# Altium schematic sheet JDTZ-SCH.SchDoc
size A1
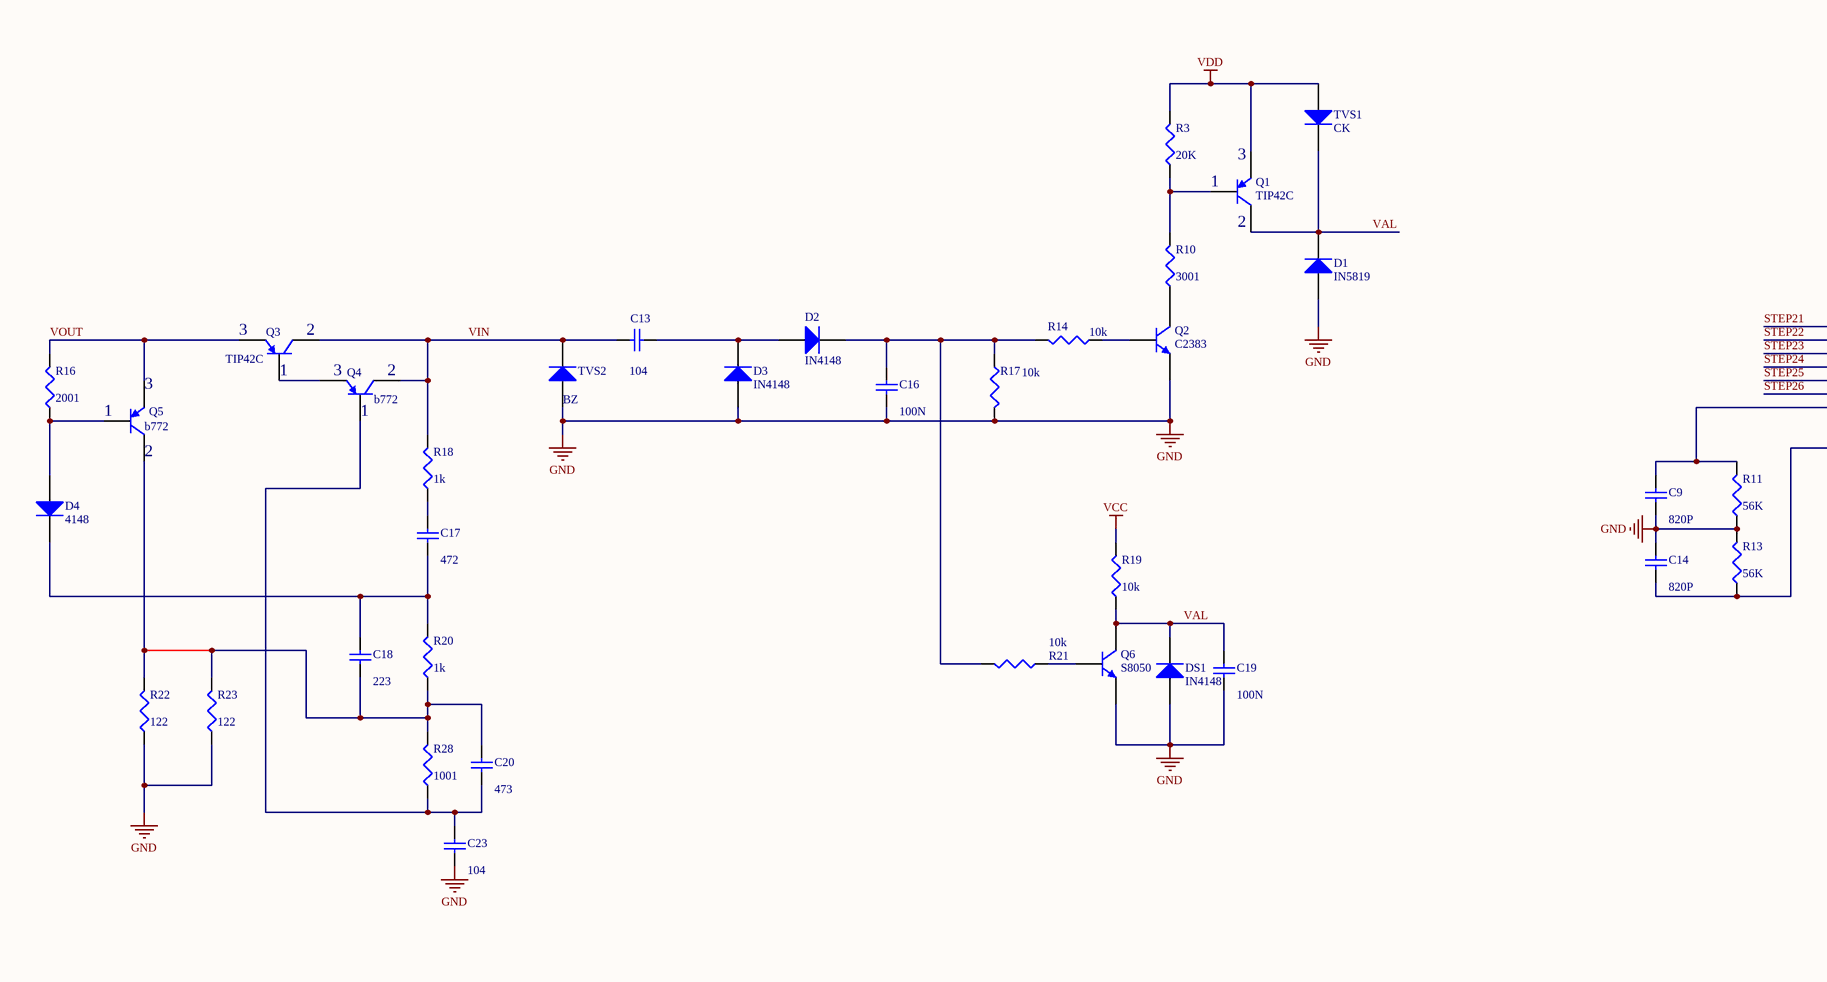
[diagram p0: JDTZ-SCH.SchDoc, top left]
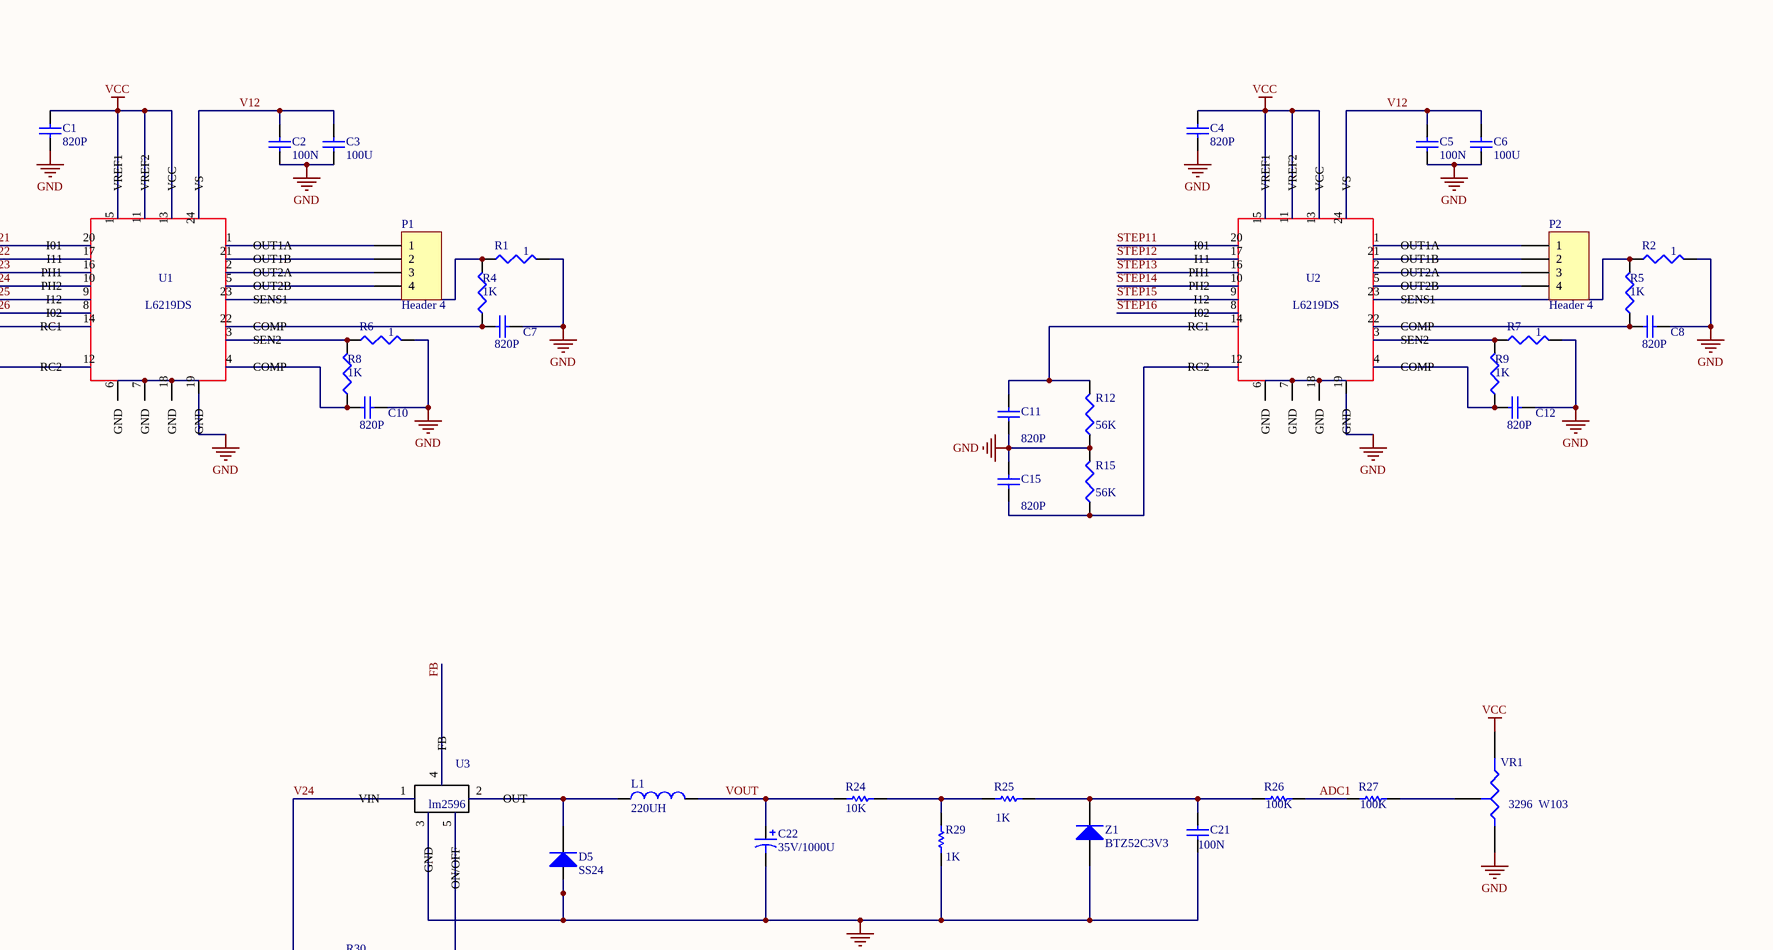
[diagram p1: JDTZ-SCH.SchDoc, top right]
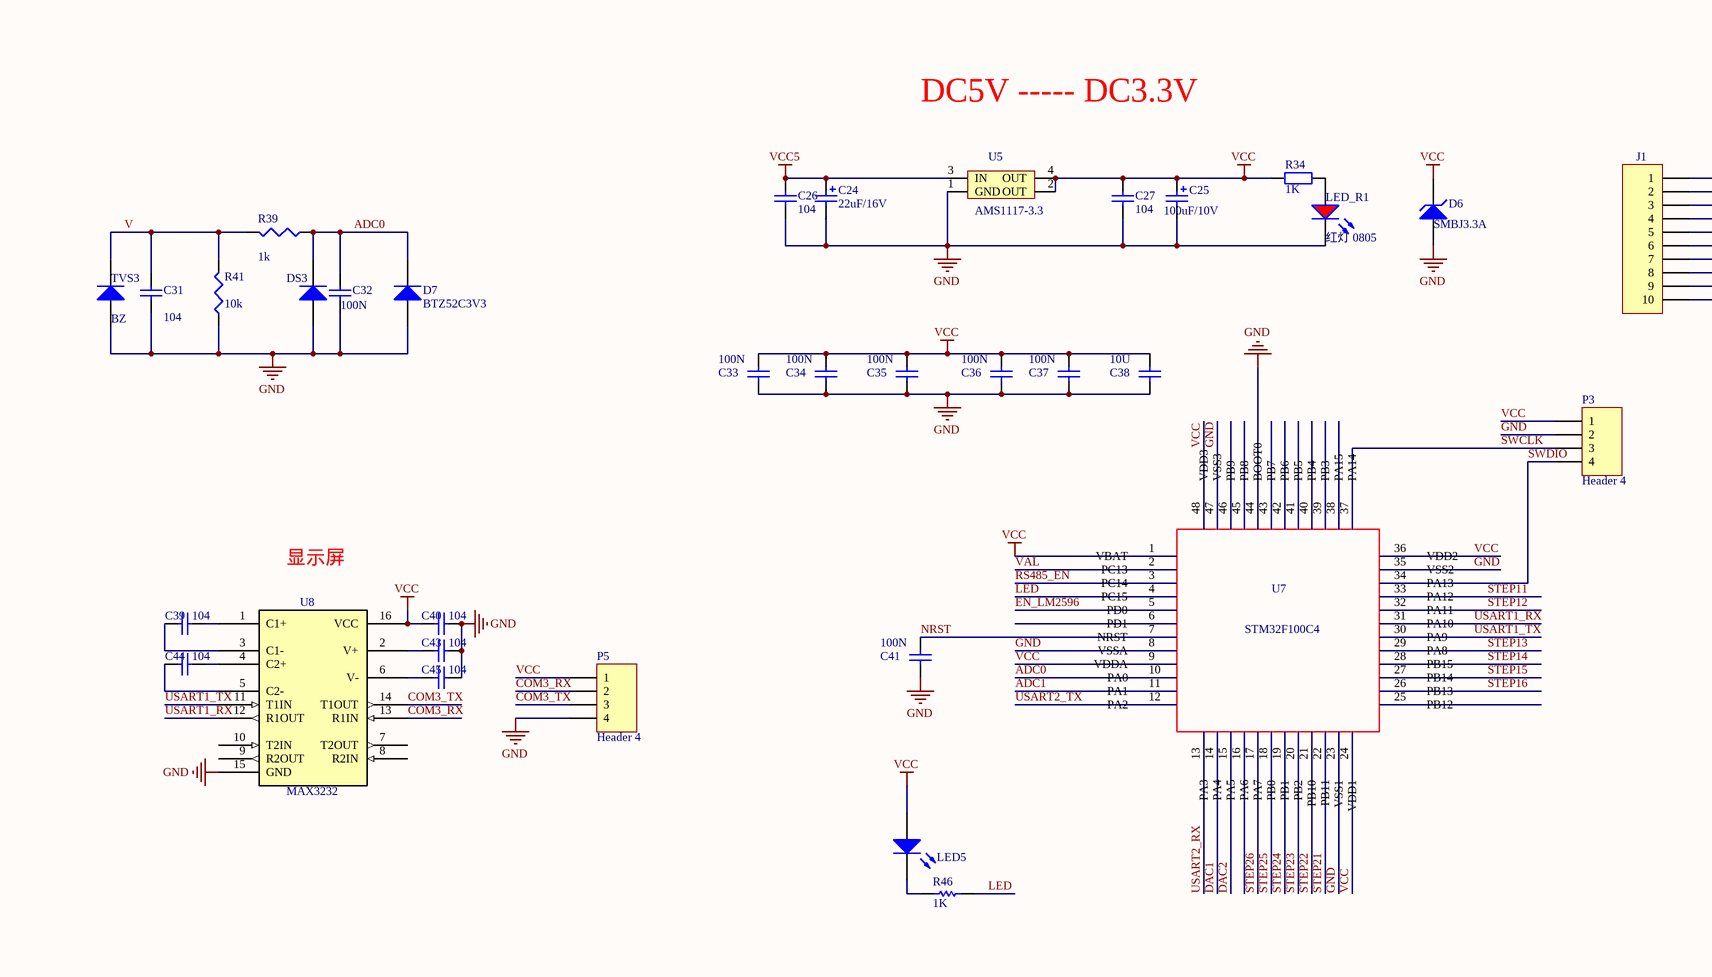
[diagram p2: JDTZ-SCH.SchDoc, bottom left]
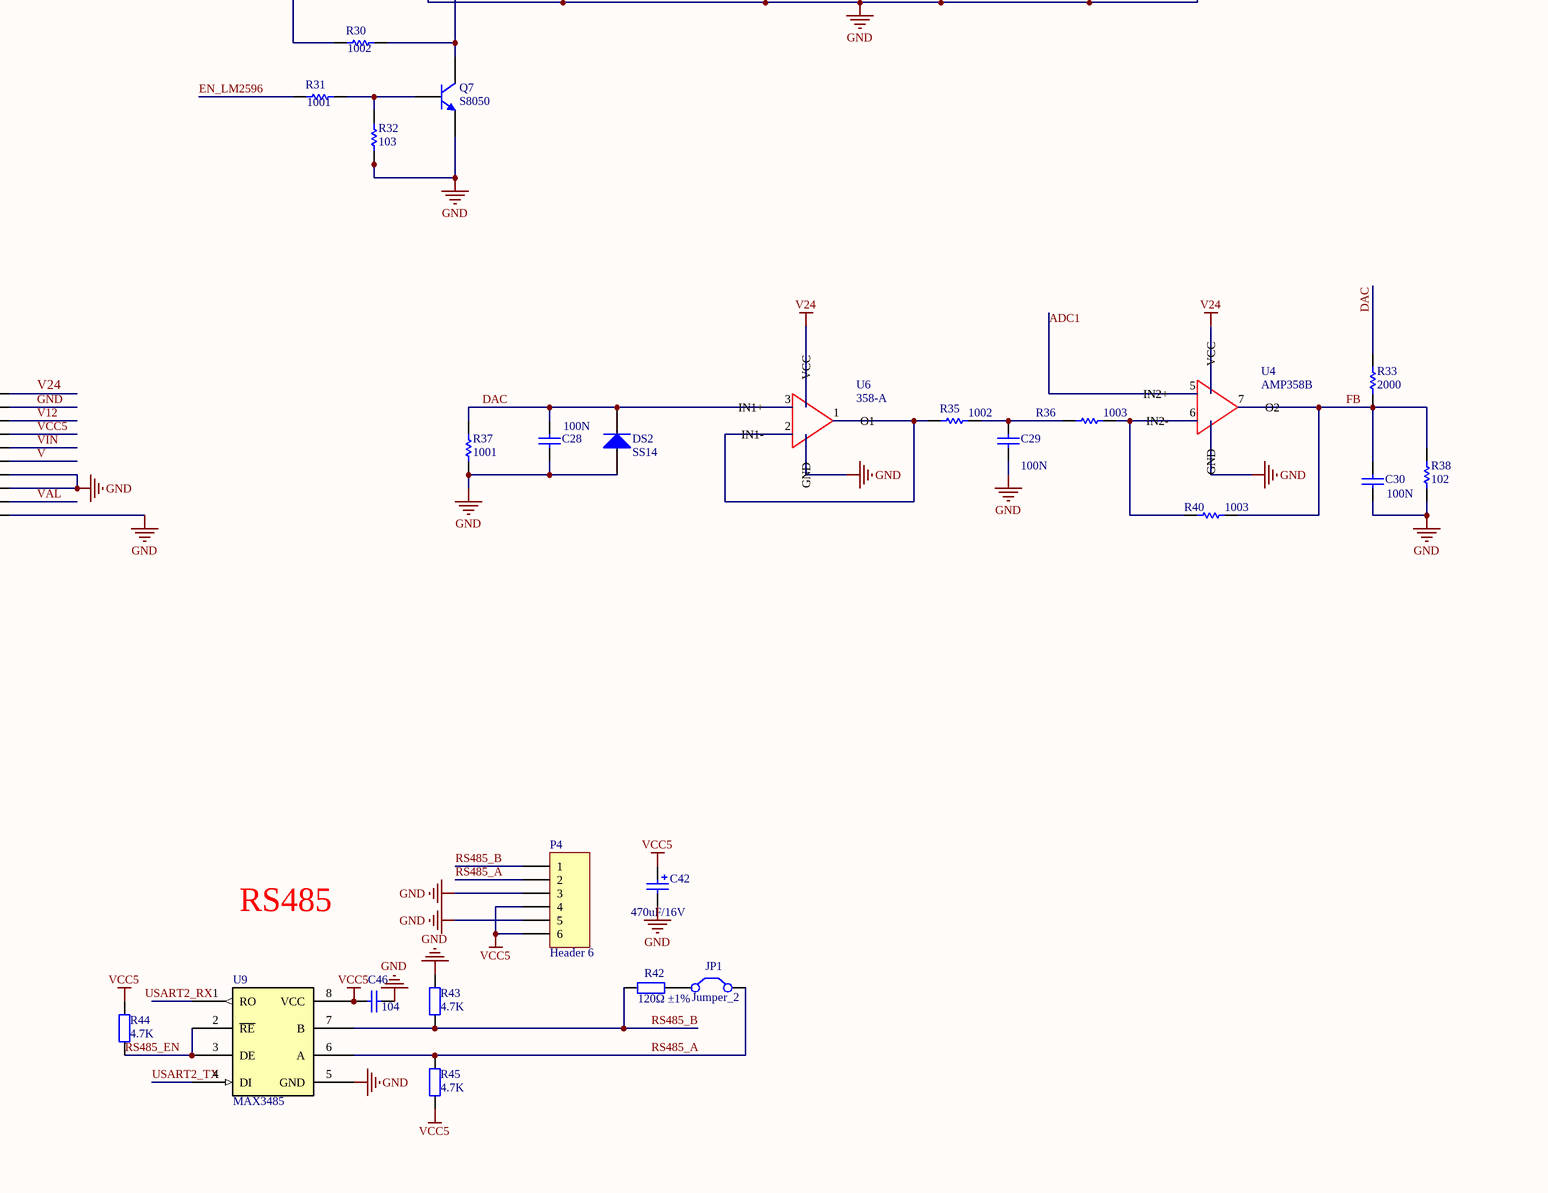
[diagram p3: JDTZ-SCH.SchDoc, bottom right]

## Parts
C1  value 820P  (hidden comment: 100N)
C2  100N
C3  value 100U  (hidden comment: 100N)
C4  value 820P  (hidden comment: 100N)
C5  100N
C6  value 100U  (hidden comment: 100N)
C7  value 820P  (hidden comment: 100N)
C8  value 820P  (hidden comment: 100N)
C9  value 820P  (hidden comment: 100N)
C10  value 820P  (hidden comment: 100N)
C11  value 820P  (hidden comment: 100N)
C12  value 820P  (hidden comment: 100N)
C13  value 104  [C1206]  (hidden comment: Cap Semi)
C14  value 820P  (hidden comment: 100N)
C15  value 820P  (hidden comment: 100N)
C16  100N  [C1206]
C17  value 472  [C1206]  (hidden comment: Cap Semi)
C18  value 223  [C1206]  (hidden comment: Cap Semi)
C19  value 100N  [C1206]  (hidden comment: Cap Semi)
C20  value 473  [C1206]  (hidden comment: Cap Semi)
C21  value 100N  [C1206]  (hidden comment: Cap Semi)
C22  value 35V/1000U  [RB7.6-15]  (hidden comment: Cap Pol1)
C23  value 104  [C1206]  (hidden comment: Cap Semi)
C24  22uF/16V  [AVX-CASE-B_3528]
C25  100uF/10V  [AVX-CASE-D_7343]
C26  104  [LC-0603_C]
C27  104  [LC-0603_C]
C28  value 100N  [C1206]  (hidden comment: Cap Semi)
C29  value 100N  [C1206]  (hidden comment: Cap Semi)
C30  value 100N  [RAD-0.3]  (hidden comment: Cap)
C31  value 104  [C1206]  (hidden comment: Cap Semi)
C32  value 100N  [C1206]  (hidden comment: Cap Semi)
C33  value 100N  [LC-0603_C]  (hidden comment: Cap Semi)
C34  value 100N  [LC-0603_C]  (hidden comment: Cap Semi)
C35  value 100N  [LC-0603_C]  (hidden comment: Cap Semi)
C36  value 100N  [LC-0603_C]  (hidden comment: Cap Semi)
C37  value 100N  [LC-0603_C]  (hidden comment: Cap Semi)
C38  value 10U  [LC-0805_R]  (hidden comment: Cap Semi)
C39  104  [LC-0603_C]
C40  104  [LC-0603_C]
C41  value 100N  [LC-0603_C]  (hidden comment: Cap Semi)
C42  470uF/16V  [CP_D_10X13]
C43  104  [LC-0603_C]
C44  104  [LC-0603_C]
C45  104  [LC-0603_C]
C46  104  [LC-0603_C]
D1  IN5819  [SOT-23]
D2  IN4148  [SOT-23]
D3  IN4148  [SOT-23]
D4  4148  [SOT-23]
D5  SS24  [SOT-23]
D6  SMBJ3.3A  [SMB(DO-214AA)]
D7  BTZ52C3V3  [DO-41]
DS1  IN4148  [SOT-23]
DS2  SS14  [SOT-23]
DS3  IN4148  [SOT-23]  (value not drawn)
J1  Header 10  [HDR1X10]  (value not drawn)
JP1  Jumper_2  [SIP2]
L1  value 220UH  [0402-A]  (hidden comment: Inductor)
LED1  LED5  [LED-1]
LED_R1  红灯 0805  [LC-0805_LED_S1]
P1  Header 4  [HDR1X4]
P2  Header 4  [HDR1X4]
P3  Header 4  [HDR1X4]
P4  Header 6  [CON_6_3.5A]
P5  Header 4  [HDR1X4]
Q1  TIP42C  [TO-92A]
Q2  C2383  [TO-92A]
Q3  TIP42C  [TO-92A]
Q4  b772  [TO-92A]
Q5  b772  [TO-92A]
Q6  S8050  [TO-92A]
Q7  S8050  [TO-92A]
R1  value 1  (hidden comment: Res3)
R2  value 1  (hidden comment: Res3)
R3  value 20K  [J1-0603]  (hidden comment: Res3)
R4  value 1K  (hidden comment: Res3)
R5  value 1K  (hidden comment: Res3)
R6  value 1  (hidden comment: Res3)
R7  value 1  (hidden comment: Res3)
R8  value 1K  (hidden comment: Res3)
R9  value 1K  (hidden comment: Res3)
R10  value 3001  [J1-0603]  (hidden comment: Res3)
R11  value 56K  (hidden comment: Res3)
R12  value 56K  (hidden comment: Res3)
R13  value 56K  (hidden comment: Res3)
R14  value 10k  [J1-0603]  (hidden comment: Res3)
R15  value 56K  (hidden comment: Res3)
R16  value 2001  [J1-0603]  (hidden comment: Res3)
R17  value 10k  [J1-0603]  (hidden comment: Res3)
R18  value 1k  [J1-0603]  (hidden comment: Res3)
R19  value 10k  [J1-0603]  (hidden comment: Res3)
R20  value 1k  [J1-0603]  (hidden comment: Res3)
R21  value 10k  [J1-0603]  (hidden comment: Res3)
R22  122  [J1-0603]
R23  122  [J1-0603]
R24  value 10K  [AXIAL-0.5]  (hidden comment: Res Semi)
R25  value 1K  [AXIAL-0.5]  (hidden comment: Res Semi)
R26  value 100K  [AXIAL-0.5]  (hidden comment: Res Semi)
R27  value 100K  [AXIAL-0.5]  (hidden comment: Res Semi)
R28  value 1001  [J1-0603]  (hidden comment: Res3)
R29  value 1K  [AXIAL-0.5]  (hidden comment: Res Semi)
R30  value 1002  [AXIAL-0.5]  (hidden comment: Res Semi)
R31  value 1001  [AXIAL-0.5]  (hidden comment: Res Semi)
R32  value 103  [AXIAL-0.5]  (hidden comment: Res Semi)
R33  value 2000  [AXIAL-0.5]  (hidden comment: Res Semi)
R34  1K  [LC-0603_R]
R35  value 1002  [AXIAL-0.5]  (hidden comment: Res Semi)
R36  value 1003  [AXIAL-0.5]  (hidden comment: Res Semi)
R37  value 1001  [AXIAL-0.5]  (hidden comment: Res Semi)
R38  value 102  [AXIAL-0.5]  (hidden comment: Res Semi)
R39  value 1k  [J1-0603]  (hidden comment: Res3)
R40  value 1003  [AXIAL-0.5]  (hidden comment: Res Semi)
R41  value 10k  [J1-0603]  (hidden comment: Res3)
R42  120Ω ±1%  [LC-0805_R]
R43  4.7K  [LC-0603_R]
R44  4.7K  [LC-0603_R]
R45  4.7K  [LC-0603_R]
R46  value 1K  [AXIAL-0.3]  (hidden comment: Res1)
TVS1  CK  [SOT-23]
TVS2  BZ  [SOT-23]
TVS3  BZ  [SOT-23]
U1  L6219DS
U2  L6219DS
U3  lm2596
U4  AMP358B
U5  AMS1117-3.3  [AMS1117]
U6  358-A
U7  STM32F100C4  [LC-LQFP-48_7x7x05P]
U8  MAX3232  [MAX3232]
U9  MAX3485  [MAX3485]
VR1  3296  W103  [VR3]
Z1  BTZ52C3V3  [SOT-23]

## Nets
GND: C1.1 C2.1 C3.1 C4.1 C5.1 C6.1 C7.2 C8.2 C9.1 C10.2 C11.1 C12.2 C14.2 C15.2 C16.1 C19.2 C21.1 C22.2 C23.1 C24.2 C25.2 C26.1 C27.1 C28.1 C29.1 C30.2 C31.1 C32.1 C33.1 C34.1 C35.1 C36.1 C37.1 C38.1 C40.1 C41.1 C42.2 C43.1 C45.1 C46.1 D1.1(A) D3.1(A) D5.1(A) D6.1(A) D7.1(A) DS1.1(A) DS2.1(A) DS3.1(A) J1.2 J1.7 J1.8 J1.10 LED_R1.K P3.2 P4.3 P4.5 P5.4 Q2.1(E) Q6.1(E) Q7.1(E) R1.2 R2.2 R6.2 R7.2 R11.1 R12.1 R13.2 R15.2 R17.2 R22.1 R23.1 R29.1 R32.1 R37.1 R38.1 R41.1 R43.2 TVS2.1(A) TVS3.1(A) U3.3(GND) U4.4(GND) U5.1(GND) U6.4(GND) U7.8(VSSA) U7.23(VSS1) U7.35(VSS2) U7.44(BOOT0) U7.47(VSS3) U8.15(GND) U9.5(GND) VR1.1(A) Z1.1(A)
V24: J1.1 R30.1 U3.1(VIN) U4.8(VCC) U6.8(VCC)
VCC: C1.2 C4.2 C25.1 C27.2 C33.2 C34.2 C35.2 C36.2 C37.2 C38.2 C40.2 D6.2(K) LED1.1(A) P3.1 P5.1 R19.2 R34.1 U1.11(VREF2) U1.13(VCC) U1.15(VREF1) U2.11(VREF2) U2.13(VCC) U2.15(VREF1) U5.2(OUT) U5.4(OUT) U7.1(VBAT) U7.9(VDDA) U7.24(VDD1) U7.36(VDD2) U7.48(VDD3) U8.16(VCC) VR1.2(B)
VCC5: C24.1 C26.2 C42.1 C46.2 J1.4 P4.4 P4.6 R44.1 R45.1 U5.3(IN) U9.8(VCC)
VDD: Q1.1(E) R3.2 TVS1.1(A)
ADC0: C32.2 D7.2(K) DS3.3(K) R39.1 U7.10(PA0)
ADC1: R26.2 R27.1 U4.5(IN2+) U7.11(PA1)
COM3_RX: P5.2 U8.13(R1IN)
COM3_TX: P5.3 U8.14(T1OUT)
DAC: C28.2 DS2.3(K) R33.2 R37.2 U6.3(IN1+)
DAC1: U7.14(PA4)
DAC2: U7.15(PA5)
EN_LM2596: R31.1 U7.5(PD0)
FB: C30.1 R33.1 R38.2 R40.2 U3.4(FB) U4.7(O2)
LED: R46.2 U7.4(PC15)
NRST: C41.2 U7.7(NRST)
RS485_A: JP1.2(C2) P4.2 R45.2 U9.6(A)
RS485_B: P4.1 R42.2 R43.1 U9.7(B)
RS485_EN: R44.2 U7.3(PC14) U9.2(~{RE}) U9.3(DE)
STEP11: U2.20(I01) U7.33(PA12)
STEP12: U2.17(I11) U7.32(PA11)
STEP13: U2.16(PH1) U7.29(PA8)
STEP14: U2.10(PH2) U7.28(PB15)
STEP15: U2.9(I12) U7.27(PB14)
STEP16: U2.8(I02) U7.26(PB13)
STEP21: U1.20(I01) U7.22(PB11)
STEP22: U1.17(I11) U7.21(PB10)
STEP23: U1.16(PH1) U7.20(PB2)
STEP24: U1.10(PH2) U7.19(PB1)
STEP25: U1.9(I12) U7.18(PB0)
STEP26: U1.8(I02) U7.17(PA7)
SWCLK: P3.3 U7.37(PA14)
SWDIO: P3.4 U7.34(PA13)
USART1_RX: U7.31(PA10) U8.12(R1OUT)
USART1_TX: U7.30(PA9) U8.11(T1IN)
USART2_RX: U7.13(PA3)
USART2_TX: U7.12(PA2) U9.4(DI)
V: C31.2 J1.6 R39.2 R41.2 TVS3.3(K)
V12: C2.2 C3.2 C5.2 C6.2 J1.3 U1.24(VS) U2.24(VS)
VAL: C19.1 D1.3(K) DS1.3(K) J1.9 Q1.3(C) Q6.3(C) R19.1 TVS1.3(K) U7.2(PC13)
VIN: C13.2 J1.5 Q3.3(C) Q4.3(C) R18.2 TVS2.3(K)
VOUT: C22.1 L1.2 Q3.1(E) Q5.1(E) R16.2 R24.2
NetC7_1: C7.1 R4.1 U1.22(COMP)
NetC8_1: C8.1 R5.1 U2.22(COMP)
NetC9_2: C9.2 R11.2 U1.14(RC1)
NetC10_1: C10.1 R8.1 U1.4(COMP)
NetC11_2: C11.2 R12.2 U2.14(RC1)
NetC12_1: C12.1 R9.1 U2.4(COMP)
NetC13_1: C13.1 D2.1(A) D3.3(K)
NetC14_1: C14.1 R13.1 U1.12(RC2)
NetC15_1: C15.1 R15.1 U2.12(RC2)
NetC16_2: C16.2 D2.3(K) R14.2 R17.1 R21.2
NetC17_1: C17.1 C18.2 D4.3(K) R20.2
NetC17_2: C17.2 R18.1
NetC18_1: C18.1 C20.2 Q5.3(C) R20.1 R22.2 R23.2 R28.2
NetC20_1: C20.1 C23.2 Q4.2(B) R28.1
NetC21_2: C21.2 R25.1 R26.1 Z1.3(K)
NetC29_2: C29.2 R35.1 R36.1
NetC39_1: C39.1 U8.1(C1+)
NetC39_2: C39.2 U8.3(C1-)
NetC43_2: C43.2 U8.2(V+)
NetC44_1: C44.1 U8.4(C2+)
NetC44_2: C44.2 U8.5(C2-)
NetC45_2: C45.2 U8.6(V-)
NetD4_1: D4.1(A) Q5.2(B) R16.1
NetD5_3: D5.3(K) L1.1 U3.2(OUT)
NetJP1_1: JP1.1(C1) R42.1
NetLED1_2: LED1.2(K) R46.1
NetLED_R1_A: LED_R1.A R34.2
NetP1_1: P1.1 U1.1(OUT1A)
NetP1_2: P1.2 U1.21(OUT1B)
NetP1_3: P1.3 U1.2(OUT2A)
NetP1_4: P1.4 U1.5(OUT2B)
NetP2_1: P2.1 U2.1(OUT1A)
NetP2_2: P2.2 U2.21(OUT1B)
NetP2_3: P2.3 U2.2(OUT2A)
NetP2_4: P2.4 U2.5(OUT2B)
NetQ1_2: Q1.2(B) R3.1 R10.2
NetQ2_2: Q2.2(B) R14.1
NetQ2_3: Q2.3(C) R10.1
NetQ3_2: Q3.2(B) Q4.1(E)
NetQ6_2: Q6.2(B) R21.1
NetQ7_2: Q7.2(B) R31.2 R32.2
NetQ7_3: Q7.3(C) R30.2 U3.5(ON/OFF)
NetR1_1: R1.1 R4.2 U1.23(SENS1)
NetR2_1: R2.1 R5.2 U2.23(SENS1)
NetR6_1: R6.1 R8.2 U1.3(SEN2)
NetR7_1: R7.1 R9.2 U2.3(SEN2)
NetR24_1: R24.1 R25.2 R29.2
NetR27_2: R27.2 VR1.3(TAP)
NetR35_2: R35.2 U6.1(O1) U6.2(IN1-)
NetR36_2: R36.2 R40.1 U4.6(IN2-)
NetU1_6: U1.6(GND) U1.7(GND) U1.18(GND) U1.19(GND)
NetU2_6: U2.6(GND) U2.7(GND) U2.18(GND) U2.19(GND)

Not connected (* = marked no-connect by the designer): U7 6(PD1) 16(PA6) 25(PB12) 38(PA15) 39(PB3) 40(PB4) 41(PB5) 42(PB6) 43(PB7) 45(PB8) 46(PB9); U8 7(T2OUT) 8(R2IN) 9(R2OUT) 10(T2IN); U9 1(RO)

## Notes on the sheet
- (near Q1) 1
- (near Q1) 3
- (near Q1) 2
- (near Q3) 3
- (near Q3) 2
- (near Q5) 1
- (near Q5) 3
- (near Q3) 1
- (near Q4) 3
- (near Q4) 1
- (near Q4) 2
- (near Q5) 2
- DC5V ----- DC3.3V
- 显示屏
- RS485
- Labels drawn without touching a wire or pin: USART2_RX

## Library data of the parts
C1-C21 C23 C28 C29 C31-C38 C41 = Cap Semi: Capacitor (Semiconductor SIM Model)
C22 = Cap Pol1: Polarized Capacitor (Radial)
C24 = Cap Pol2: Polarized Capacitor (Axial); 厂商: AVX; 名称: 钽电容; 封装: CASE-B_3528
C25 = Cap Pol2: Polarized Capacitor (Axial); 厂商: AVX; 名称: 钽电容; 封装: CASE-D_7343
C26 C27 C39 C40 C43-C46 = 0603 100nF (104) 10% 50V: 贴片电容; 封装: 0603
C30 = Cap: Capacitor
C42 = Cap Pol2: Polarized Capacitor (Axial); 厂商: CapXon（台湾丰宾）; 名称: 直插电解电容; 封装: 10 X 13
D1-D5 DS1-DS3 TVS1-TVS3 Z1 = Diode BAS21: Silicon Switching Diode for High-Speed, High-Voltage Switching; Note: Pin 2 is not connected and not drawn.
D6 = SMBJ3.3A: 名称: TVS; 品牌: Brightking(台湾君耀)
D7 = Diode 1N4001: 1 Amp General Purpose Rectifier
J1 = Header 10: Header, 10-Pin
JP1 = Jumper_2: Jumper Wire
L1 = Inductor: Code_IEC: 1005
LED1 = LED1: Typical RED GaAs LED
LED_R1 = 0805 红灯: 发光二极管
P1-P3 P5 = Header 4: Header, 4-Pin
P4 = Header 6: Header, 6-Pin
Q1 Q3-Q5 = 2N3906: PNP General Purpose Amplifier
Q2 Q6 Q7 = 2N3904: NPN General Purpose Amplifier
R1-R23 R28 R39 R41 = Res3: Resistor
R24-R27 R29-R33 R35-R38 R40 = Res Semi: Semiconductor Resistor
R34 = Res0805: Resistor; 封装: 0603; 厂商: 国巨; 名称: 电阻
R42 = 0603 750Ω (7500) 1%: 贴片电阻; 封装: 1206; 品牌: LC
R43-R45 = 0603 750Ω (7500) 1%: 贴片电阻; 封装: 0603; 品牌: LC
R46 = Res1: Resistor
U5 = AMS1117: 厂商: 美国AMS; 名称: 电源芯片; 封装: SOT-223
U6 = AMP358
U8 = MAX3232: 封装: SOIC-16_150mil; 名称: RS232收发器; 品牌: MAXIM(美信)
U9 = MAX3485: 名称: RS485收发器; 品牌: MAXIM(美信); 封装: SOIC-8_150mil
VR1 = Res Tap: Tapped Resistor; Sim Note: Enter the Resistance value and the set point into parameter fields.; Set Position: 0.5; Value: 103K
